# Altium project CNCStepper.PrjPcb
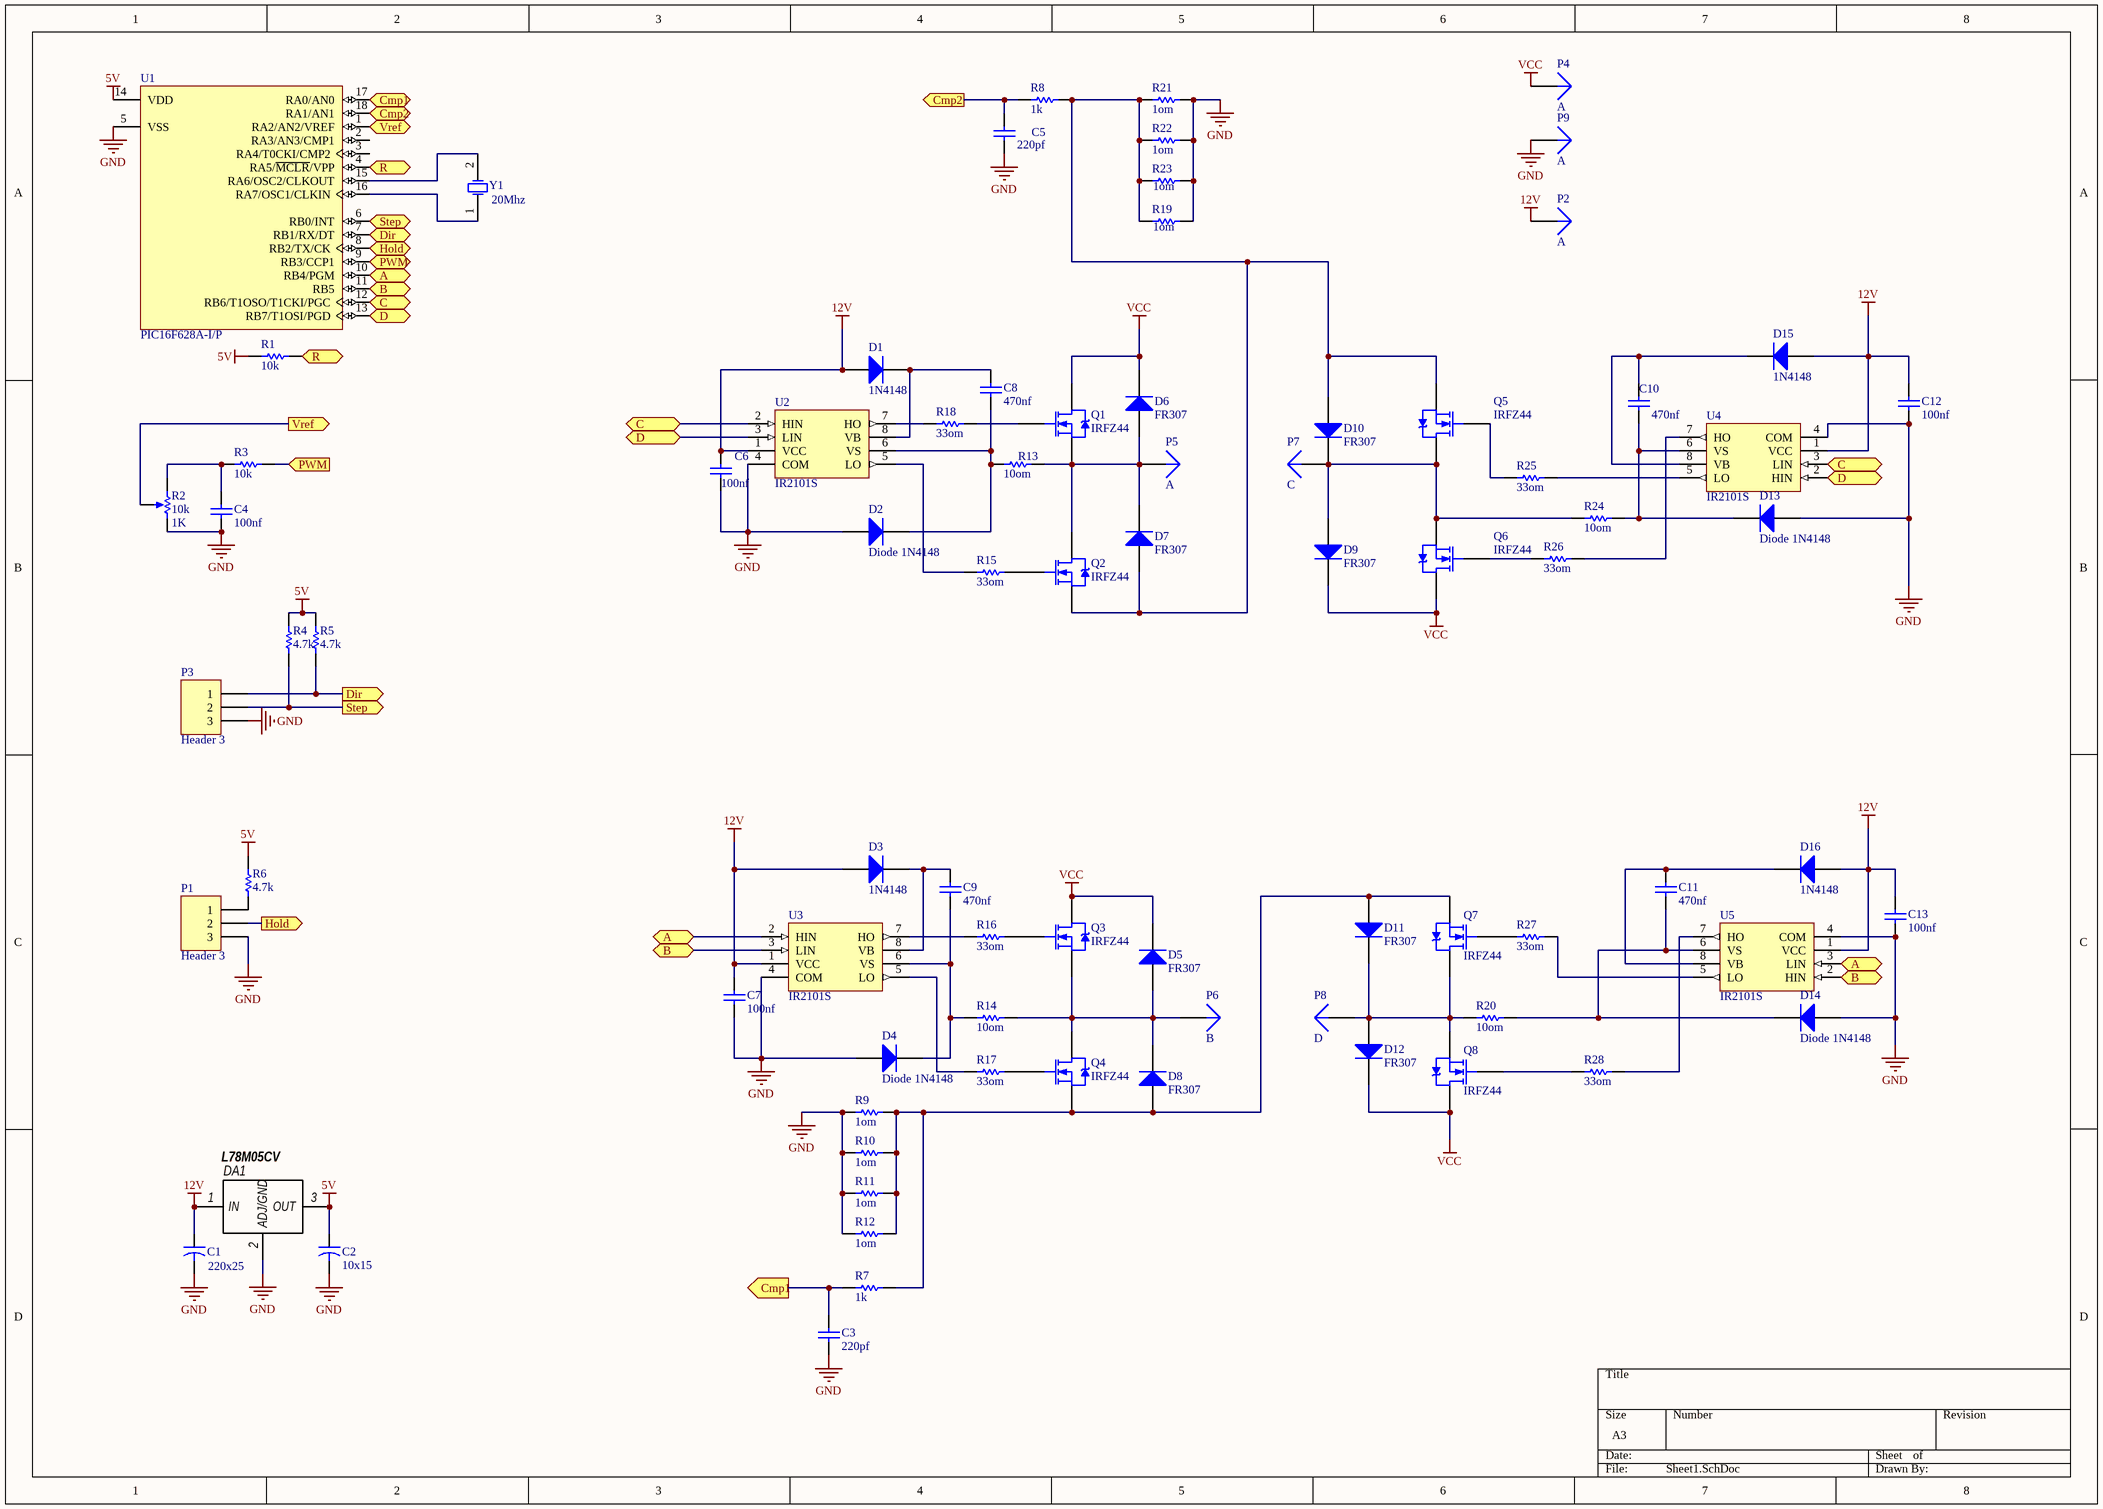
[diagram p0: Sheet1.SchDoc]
1 sheet, 81 parts. Net scope: flat (ports and power ports of the same name join across sheets).
Board file: PCB1.PcbDoc

## Sheet Sheet1.SchDoc
size A3

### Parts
C1  220x25  [CAPR5-4X5]
C2  10x15  [CAPR5-4X5]
C3  220pf  [1206]
C4  100nf  [1206]
C5  220pf  [1206]
C6  100nf  [1206]
C7  100nf  [1206]
C8  470nf  [1206]
C9  470nf  [1206]
C10  470nf  [1206]
C11  470nf  [1206]
C12  100nf  [1206]
C13  100nf  [1206]
D1  1N4148  [DO-35]
D2  Diode 1N4148  [DO-35]
D3  1N4148  [DO-35]
D4  Diode 1N4148  [DO-35]
D5  FR307  [DO-41]
D6  FR307  [DO-41]
D7  FR307  [DO-41]
D8  FR307  [DO-41]
D9  FR307  [DO-41]
D10  FR307  [DO-41]
D11  FR307  [DO-41]
D12  FR307  [DO-41]
D13  Diode 1N4148  [DO-35]
D14  Diode 1N4148  [DO-35]
D15  1N4148  [DO-35]
D16  1N4148  [DO-35]
DA1  L78M05CV  [TO-220A]
P1  Header 3  [HDR1X3]
P2  A  [PIN1]
P3  Header 3  [HDR1X3]
P4  A  [PIN1]
P5  A  [PIN1]
P6  B  [PIN1]
P7  C  [PIN1]
P8  D  [PIN1]
P9  A  [PIN1]
Q1  IRFZ44  [TO-220AB]
Q2  IRFZ44  [TO-220AB]
Q3  IRFZ44  [TO-220AB]
Q4  IRFZ44  [TO-220AB]
Q5  IRFZ44  [TO-220AB]
Q6  IRFZ44  [TO-220AB]
Q7  IRFZ44  [TO-220AB]
Q8  IRFZ44  [TO-220AB]
R1  10k  [6-0805]
R2  10k  value 1K  [VR5]
R3  10k  [6-0805]
R4  4.7k  [6-0805]
R5  4.7k  [6-0805]
R6  4.7k  [6-0805]
R7  1k  [6-0805]
R8  1k  [6-0805]
R9  1om  [1T-2512]
R10  1om  [1T-2512]
R11  1om  [1T-2512]
R12  1om  [1T-2512]
R13  10om  [6-0805]
R14  10om  [6-0805]
R15  33om  [6-0805]
R16  33om  [6-0805]
R17  33om  [6-0805]
R18  33om  [6-0805]
R19  1om  [1T-2512]
R20  10om  [6-0805]
R21  1om  [1T-2512]
R22  1om  [1T-2512]
R23  1om  [1T-2512]
R24  10om  [6-0805]
R25  33om  [6-0805]
R26  33om  [6-0805]
R27  33om  [6-0805]
R28  33om  [6-0805]
U1  PIC16F628A-I/P  [PDIP300-P18]
U2  IR2101S  [SO-8_N]
U3  IR2101S  [SO-8_N]
U4  IR2101S  [SO-8_N]
U5  IR2101S  [SO-8_N]
Y1  20Mhz  [R38]

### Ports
A, B, C, Cmp1 (in), Cmp1 (out), Cmp2 (in), Cmp2 (out), D, Dir (in), Dir (out), Hold (in), Hold (out), PWM (in), PWM (out), R (in), R (out), Step (in), Step (out), Vref (in), Vref (out)

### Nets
5V: C2.1 DA1.3(OUT) R1.1 R4.2 R5.2 R6.2 U1.14(VDD)
12V: C1.1 C6.2 C7.2 C12.2 C13.2 D1.1(A) D3.1(A) D15.1(A) D16.1(A) DA1.1(IN) P2.1 U2.1(VCC) U3.1(VCC) U4.1(VCC) U5.1(VCC)
GND: C1.2 C2.2 C3.1 C4.1 C5.1 C6.1 C7.1 C12.1 C13.1 D2.1(A) D4.1(A) D13.1(A) D14.1(A) DA1.2(ADJ/GND) P1.3 P3.3 P9.1 R2.2(BOT) R9.1 R10.1 R11.1 R12.1 R19.2 R21.2 R22.2 R23.2 U1.5(VSS) U2.4(COM) U3.4(COM) U4.4(COM) U5.4(COM)
VCC: D5.2(K) D6.2(K) D9.2(K) D12.2(K) P4.1 Q1.2(D) Q3.2(D) Q6.2(D) Q8.2(D)
NetC3_2: C3.2 R7.1 U1.17(RA0/AN0) ; port Cmp1
NetC4_2: C4.2 R2.1(TOP) R3.1
NetC5_2: C5.2 R8.1 U1.18(RA1/AN1) ; port Cmp2
NetC8_1: C8.1 D2.2(K) R13.1 U2.6(VS)
NetC8_2: C8.2 D1.2(K) U2.8(VB)
NetC9_1: C9.1 D4.2(K) R14.1 U3.6(VS)
NetC9_2: C9.2 D3.2(K) U3.8(VB)
NetC10_1: C10.1 D13.2(K) R24.2 U4.6(VS)
NetC10_2: C10.2 D15.2(K) U4.8(VB)
NetC11_1: C11.1 D14.2(K) R20.2 U5.6(VS)
NetC11_2: C11.2 D16.2(K) U5.8(VB)
NetD5_1: D5.1(A) D8.2(K) P6.1 Q3.3(S) Q4.2(D) R14.2
NetD6_1: D6.1(A) D7.2(K) P5.1 Q1.3(S) Q2.2(D) R13.2
NetD7_1: D7.1(A) D10.1(A) Q2.3(S) Q5.3(S) R8.2 R19.1 R21.1 R22.1 R23.1
NetD8_1: D8.1(A) D11.1(A) Q4.3(S) Q7.3(S) R7.2 R9.2 R10.2 R11.2 R12.2
NetD9_1: D9.1(A) D10.2(K) P7.1 Q5.2(D) Q6.3(S) R24.1
NetD11_2: D11.2(K) D12.1(A) P8.1 Q7.2(D) Q8.3(S) R20.1
NetP1_1: P1.1 R6.1
NetP1_2: P1.2 U1.8(RB2/TX/CK) ; port Hold
NetP3_1: P3.1 R5.1 U1.7(RB1/RX/DT) ; port Dir
NetP3_2: P3.2 R4.1 U1.6(RB0/INT) ; port Step
NetQ1_1: Q1.1(G) R18.2
NetQ2_1: Q2.1(G) R15.2
NetQ3_1: Q3.1(G) R16.2
NetQ4_1: Q4.1(G) R17.2
NetQ5_1: Q5.1(G) R25.1
NetQ6_1: Q6.1(G) R26.1
NetQ7_1: Q7.1(G) R27.1
NetQ8_1: Q8.1(G) R28.1
NetR1_2: R1.2 U1.4(RA5/~{MCLR}/VPP) ; port R
NetR2_3: R2.3(TAP) U1.1(RA2/AN2/VREF) ; port Vref
NetR3_2: R3.2 U1.9(RB3/CCP1) ; port PWM
NetR15_1: R15.1 U2.5(LO)
NetR16_1: R16.1 U3.7(HO)
NetR17_1: R17.1 U3.5(LO)
NetR18_1: R18.1 U2.7(HO)
NetR25_2: R25.2 U4.5(LO)
NetR26_2: R26.2 U4.7(HO)
NetR27_2: R27.2 U5.5(LO)
NetR28_2: R28.2 U5.7(HO)
NetU1_10: U1.10(RB4/PGM) U3.2(HIN) U5.3(LIN) ; port A
NetU1_11: U1.11(RB5) U3.3(LIN) U5.2(HIN) ; port B
NetU1_12: U1.12(RB6/T1OSO/T1CKI/PGC) U2.2(HIN) U4.3(LIN) ; port C
NetU1_13: U1.13(RB7/T1OSI/PGD) U2.3(LIN) U4.2(HIN) ; port D
NetU1_15: U1.15(RA6/OSC2/CLKOUT) Y1.2(OSC2)
NetU1_16: U1.16(RA7/OSC1/CLKIN) Y1.1(OSC1)

Not connected (* = marked no-connect by the designer): U1 2(RA3/AN3/CMP1) 3(RA4/T0CKI/CMP2)

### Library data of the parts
C1 C2 = Cap2: Capacitor
C3-C13 = C1206: Ceramic Chip Capacitor - Standard
D1-D4 D13-D16 = Diode 1N4148: High Conductance Fast Diode
D5-D12 = Diode 1N4007: 1 Amp General Purpose Rectifier
DA1 = L78M05CV: Manufacturer: STMicroelectronics; ValueBOM: 5В 500мА
P1 P3 = Header 3: Header, 3-Pin
P2 P4-P9 = Plug
Q1-Q8 = IRFZ44: HEXFET N-Channel Power MOSFET; Note: Pin 2 is electrically connected to pin 4.
R1 R3-R8 R13-R18 R20 R24-R28 = ERJ6RB: Precision Thick Film Chip Resistor, 10 Ohm to 1M Ohm Range, 1% and 0.5% Tolerance, 0805 Size, 0.1 W
R2 = RPot: Potentiometer; pin to pad: 2>3 3>2; Sim Note: Enter the Resistance value and the set point into parameter fields.; Set Position: 0.5
R9-R12 R19 R21-R23 = ERJ1TRS: Low Ohmic Value Thick Film Chip Resistor, 0.1 Ohm to 0.2 Ohm Range, 1%, 2% and 5% Tolerance, 2512 Size, 1 W
U1 = PIC16F628A-I/P: FLASH-Based 8-Bit CMOS Microcontroller with nanoWatt Technology, 2K (x14-Bit words) FLASH, 224 Bytes SRAM, 18-Pin PDIP, 3.0 to 5.5V Supply Range, Industrial Temperature
U2-U5 = IR2101S: High and Low Side Driver
Y1 = XTAL: Crystal Oscillator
